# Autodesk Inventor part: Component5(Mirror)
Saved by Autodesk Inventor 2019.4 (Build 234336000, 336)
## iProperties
Created: 2020-06
Part Number: Component5(Mirror)
Material: Generic
Document SubType Name: Modeling
Designer: Administrator
Density: 1 g/cm^3
Appearance: Default
Title: Component5(Mirror)
Author: Administrator
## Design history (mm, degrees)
